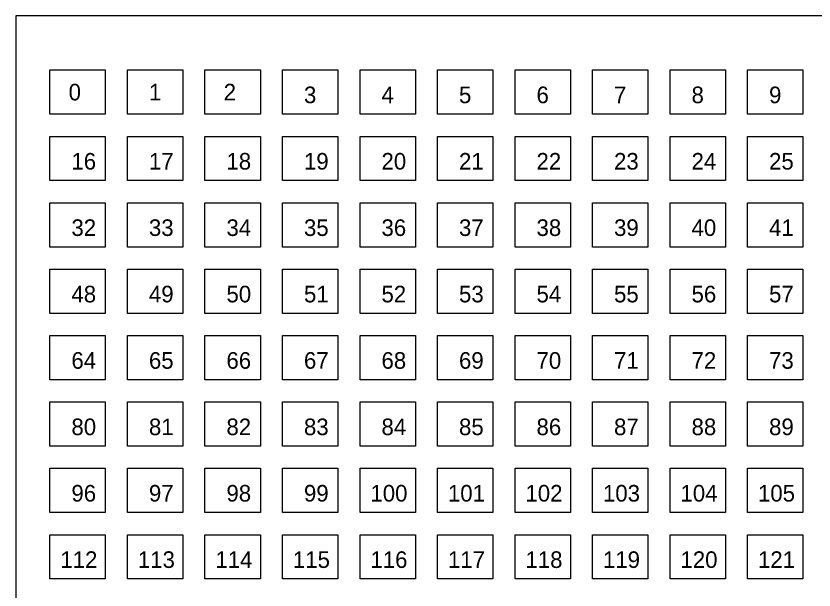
# Model space of a CAD drawing. Extents: x 11193 to 12507, y 10092 to 10555.
# Drawn here: x 11927 to 12215.3, y 10335 to 10542.6 of the extents above; entities that cross this region are included whole.
import ezdxf

# ---------------------------------------------------------------- set-up
doc = ezdxf.new("R2010")
doc.units = 0
for name, color, linetype in [('Level 1', 7, 'Continuous'), ('Level 3', 7, 'Continuous'), ('Level 62', 7, 'Continuous'), ('Level 63', 7, 'Continuous')]:
    doc.layers.add(name, color=color, linetype=linetype)

msp = doc.modelspace()

# ---------------------------------------------------------------- linework, layer by layer
at = {"layer": 'Level 1'}
msp.add_lwpolyline([(11939.26, 10459.04), (11939.26, 10475.04), (11959.26, 10475.04), (11959.26, 10459.04)], close=True, dxfattribs=at)
msp.add_lwpolyline([(11939.26, 10459.04), (11939.26, 10475.04), (11959.26, 10475.04), (11959.26, 10459.04)], close=True, dxfattribs=at)
at = {"layer": 'Level 3'}
msp.add_lwpolyline([(11926.98, 10137.56), (12506.98, 10137.56), (12506.98, 10542.56), (11926.98, 10542.56), (11926.98, 10137.56)], dxfattribs=at)
for points in [[(11939.26, 10507.04), (11939.26, 10523.04), (11959.26, 10523.04), (11959.26, 10507.04)], [(11967.26, 10507.04), (11967.26, 10523.04), (11987.26, 10523.04), (11987.26, 10507.04)], [(11995.26, 10507.04), (11995.26, 10523.04), (12015.26, 10523.04), (12015.26, 10507.04)], [(12023.26, 10507.04), (12023.26, 10523.04), (12043.26, 10523.04), (12043.26, 10507.04)], [(12051.26, 10507.04), (12051.26, 10523.04), (12071.26, 10523.04), (12071.26, 10507.04)], [(12079.26, 10507.04), (12079.26, 10523.04), (12099.26, 10523.04), (12099.26, 10507.04)], [(12107.26, 10507.04), (12107.26, 10523.04), (12127.26, 10523.04), (12127.26, 10507.04)], [(12135.26, 10507.04), (12135.26, 10523.04), (12155.26, 10523.04), (12155.26, 10507.04)], [(12163.26, 10507.04), (12163.26, 10523.04), (12183.26, 10523.04), (12183.26, 10507.04)], [(12191.26, 10507.04), (12191.26, 10523.04), (12211.26, 10523.04), (12211.26, 10507.04)], [(11939.26, 10483.04), (11939.26, 10499.04), (11959.26, 10499.04), (11959.26, 10483.04)], [(11967.26, 10483.04), (11967.26, 10499.04), (11987.26, 10499.04), (11987.26, 10483.04)], [(11995.26, 10483.04), (11995.26, 10499.04), (12015.26, 10499.04), (12015.26, 10483.04)], [(12023.26, 10483.04), (12023.26, 10499.04), (12043.26, 10499.04), (12043.26, 10483.04)], [(12051.26, 10483.04), (12051.26, 10499.04), (12071.26, 10499.04), (12071.26, 10483.04)], [(12079.26, 10483.04), (12079.26, 10499.04), (12099.26, 10499.04), (12099.26, 10483.04)], [(12107.26, 10483.04), (12107.26, 10499.04), (12127.26, 10499.04), (12127.26, 10483.04)], [(12135.26, 10483.04), (12135.26, 10499.04), (12155.26, 10499.04), (12155.26, 10483.04)], [(12163.26, 10483.04), (12163.26, 10499.04), (12183.26, 10499.04), (12183.26, 10483.04)], [(12191.26, 10483.04), (12191.26, 10499.04), (12211.26, 10499.04), (12211.26, 10483.04)], [(11967.26, 10459.04), (11967.26, 10475.04), (11987.26, 10475.04), (11987.26, 10459.04)], [(11995.26, 10459.04), (11995.26, 10475.04), (12015.26, 10475.04), (12015.26, 10459.04)], [(12023.26, 10459.04), (12023.26, 10475.04), (12043.26, 10475.04), (12043.26, 10459.04)], [(12051.26, 10459.04), (12051.26, 10475.04), (12071.26, 10475.04), (12071.26, 10459.04)], [(12079.26, 10459.04), (12079.26, 10475.04), (12099.26, 10475.04), (12099.26, 10459.04)], [(12107.26, 10459.04), (12107.26, 10475.04), (12127.26, 10475.04), (12127.26, 10459.04)], [(12135.26, 10459.04), (12135.26, 10475.04), (12155.26, 10475.04), (12155.26, 10459.04)], [(12163.26, 10459.04), (12163.26, 10475.04), (12183.26, 10475.04), (12183.26, 10459.04)], [(12191.26, 10459.04), (12191.26, 10475.04), (12211.26, 10475.04), (12211.26, 10459.04)], [(11939.26, 10435.04), (11939.26, 10451.04), (11959.26, 10451.04), (11959.26, 10435.04)], [(11967.26, 10435.04), (11967.26, 10451.04), (11987.26, 10451.04), (11987.26, 10435.04)], [(11995.26, 10435.04), (11995.26, 10451.04), (12015.26, 10451.04), (12015.26, 10435.04)], [(12023.26, 10435.04), (12023.26, 10451.04), (12043.26, 10451.04), (12043.26, 10435.04)], [(12051.26, 10435.04), (12051.26, 10451.04), (12071.26, 10451.04), (12071.26, 10435.04)], [(12079.26, 10435.04), (12079.26, 10451.04), (12099.26, 10451.04), (12099.26, 10435.04)], [(12107.26, 10435.04), (12107.26, 10451.04), (12127.26, 10451.04), (12127.26, 10435.04)], [(12135.26, 10435.04), (12135.26, 10451.04), (12155.26, 10451.04), (12155.26, 10435.04)], [(12163.26, 10435.04), (12163.26, 10451.04), (12183.26, 10451.04), (12183.26, 10435.04)], [(12191.26, 10435.04), (12191.26, 10451.04), (12211.26, 10451.04), (12211.26, 10435.04)], [(11939.26, 10411.04), (11939.26, 10427.04), (11959.26, 10427.04), (11959.26, 10411.04)], [(11967.26, 10411.04), (11967.26, 10427.04), (11987.26, 10427.04), (11987.26, 10411.04)], [(11995.26, 10411.04), (11995.26, 10427.04), (12015.26, 10427.04), (12015.26, 10411.04)], [(12023.26, 10411.04), (12023.26, 10427.04), (12043.26, 10427.04), (12043.26, 10411.04)], [(12051.26, 10411.04), (12051.26, 10427.04), (12071.26, 10427.04), (12071.26, 10411.04)], [(12079.26, 10411.04), (12079.26, 10427.04), (12099.26, 10427.04), (12099.26, 10411.04)], [(12107.26, 10411.04), (12107.26, 10427.04), (12127.26, 10427.04), (12127.26, 10411.04)], [(12135.26, 10411.04), (12135.26, 10427.04), (12155.26, 10427.04), (12155.26, 10411.04)], [(12163.26, 10411.04), (12163.26, 10427.04), (12183.26, 10427.04), (12183.26, 10411.04)], [(12191.26, 10411.04), (12191.26, 10427.04), (12211.26, 10427.04), (12211.26, 10411.04)], [(11939.26, 10387.04), (11939.26, 10403.04), (11959.26, 10403.04), (11959.26, 10387.04)], [(11967.26, 10387.04), (11967.26, 10403.04), (11987.26, 10403.04), (11987.26, 10387.04)], [(11995.26, 10387.04), (11995.26, 10403.04), (12015.26, 10403.04), (12015.26, 10387.04)], [(12023.26, 10387.04), (12023.26, 10403.04), (12043.26, 10403.04), (12043.26, 10387.04)], [(12051.26, 10387.04), (12051.26, 10403.04), (12071.26, 10403.04), (12071.26, 10387.04)], [(12079.26, 10387.04), (12079.26, 10403.04), (12099.26, 10403.04), (12099.26, 10387.04)], [(12107.26, 10387.04), (12107.26, 10403.04), (12127.26, 10403.04), (12127.26, 10387.04)], [(12135.26, 10387.04), (12135.26, 10403.04), (12155.26, 10403.04), (12155.26, 10387.04)], [(12163.26, 10387.04), (12163.26, 10403.04), (12183.26, 10403.04), (12183.26, 10387.04)], [(12191.26, 10387.04), (12191.26, 10403.04), (12211.26, 10403.04), (12211.26, 10387.04)], [(11939.26, 10363.04), (11939.26, 10379.04), (11959.26, 10379.04), (11959.26, 10363.04)], [(11967.26, 10363.04), (11967.26, 10379.04), (11987.26, 10379.04), (11987.26, 10363.04)], [(11995.26, 10363.04), (11995.26, 10379.04), (12015.26, 10379.04), (12015.26, 10363.04)], [(12023.26, 10363.04), (12023.26, 10379.04), (12043.26, 10379.04), (12043.26, 10363.04)], [(12051.26, 10363.04), (12051.26, 10379.04), (12071.26, 10379.04), (12071.26, 10363.04)], [(12079.26, 10363.04), (12079.26, 10379.04), (12099.26, 10379.04), (12099.26, 10363.04)], [(12107.26, 10363.04), (12107.26, 10379.04), (12127.26, 10379.04), (12127.26, 10363.04)], [(12135.26, 10363.04), (12135.26, 10379.04), (12155.26, 10379.04), (12155.26, 10363.04)], [(12163.26, 10363.04), (12163.26, 10379.04), (12183.26, 10379.04), (12183.26, 10363.04)], [(12191.26, 10363.04), (12191.26, 10379.04), (12211.26, 10379.04), (12211.26, 10363.04)], [(11939.26, 10339.04), (11939.26, 10355.04), (11959.26, 10355.04), (11959.26, 10339.04)], [(11967.26, 10339.04), (11967.26, 10355.04), (11987.26, 10355.04), (11987.26, 10339.04)], [(11995.26, 10339.04), (11995.26, 10355.04), (12015.26, 10355.04), (12015.26, 10339.04)], [(12023.26, 10339.04), (12023.26, 10355.04), (12043.26, 10355.04), (12043.26, 10339.04)], [(12051.26, 10339.04), (12051.26, 10355.04), (12071.26, 10355.04), (12071.26, 10339.04)], [(12079.26, 10339.04), (12079.26, 10355.04), (12099.26, 10355.04), (12099.26, 10339.04)], [(12107.26, 10339.04), (12107.26, 10355.04), (12127.26, 10355.04), (12127.26, 10339.04)], [(12135.26, 10339.04), (12135.26, 10355.04), (12155.26, 10355.04), (12155.26, 10339.04)], [(12163.26, 10339.04), (12163.26, 10355.04), (12183.26, 10355.04), (12183.26, 10339.04)], [(12191.26, 10339.04), (12191.26, 10355.04), (12211.26, 10355.04), (12211.26, 10339.04)]]:
    msp.add_lwpolyline(points, close=True, dxfattribs=at)
at = {"layer": 'Level 63'}
for points in [[(11939.26, 10507.04), (11939.26, 10523.04), (11959.26, 10523.04), (11959.26, 10507.04)], [(11967.26, 10507.04), (11967.26, 10523.04), (11987.26, 10523.04), (11987.26, 10507.04)], [(11995.26, 10507.04), (11995.26, 10523.04), (12015.26, 10523.04), (12015.26, 10507.04)], [(12023.26, 10507.04), (12023.26, 10523.04), (12043.26, 10523.04), (12043.26, 10507.04)], [(12051.26, 10507.04), (12051.26, 10523.04), (12071.26, 10523.04), (12071.26, 10507.04)], [(12079.26, 10507.04), (12079.26, 10523.04), (12099.26, 10523.04), (12099.26, 10507.04)], [(12107.26, 10507.04), (12107.26, 10523.04), (12127.26, 10523.04), (12127.26, 10507.04)], [(12135.26, 10507.04), (12135.26, 10523.04), (12155.26, 10523.04), (12155.26, 10507.04)], [(12163.26, 10507.04), (12163.26, 10523.04), (12183.26, 10523.04), (12183.26, 10507.04)], [(12191.26, 10507.04), (12191.26, 10523.04), (12211.26, 10523.04), (12211.26, 10507.04)], [(11939.26, 10483.04), (11939.26, 10499.04), (11959.26, 10499.04), (11959.26, 10483.04)], [(11967.26, 10483.04), (11967.26, 10499.04), (11987.26, 10499.04), (11987.26, 10483.04)], [(11995.26, 10483.04), (11995.26, 10499.04), (12015.26, 10499.04), (12015.26, 10483.04)], [(12023.26, 10483.04), (12023.26, 10499.04), (12043.26, 10499.04), (12043.26, 10483.04)], [(12051.26, 10483.04), (12051.26, 10499.04), (12071.26, 10499.04), (12071.26, 10483.04)], [(12079.26, 10483.04), (12079.26, 10499.04), (12099.26, 10499.04), (12099.26, 10483.04)], [(12107.26, 10483.04), (12107.26, 10499.04), (12127.26, 10499.04), (12127.26, 10483.04)], [(12135.26, 10483.04), (12135.26, 10499.04), (12155.26, 10499.04), (12155.26, 10483.04)], [(12163.26, 10483.04), (12163.26, 10499.04), (12183.26, 10499.04), (12183.26, 10483.04)], [(12191.26, 10483.04), (12191.26, 10499.04), (12211.26, 10499.04), (12211.26, 10483.04)], [(11939.26, 10459.04), (11939.26, 10475.04), (11959.26, 10475.04), (11959.26, 10459.04)], [(11967.26, 10459.04), (11967.26, 10475.04), (11987.26, 10475.04), (11987.26, 10459.04)], [(11995.26, 10459.04), (11995.26, 10475.04), (12015.26, 10475.04), (12015.26, 10459.04)], [(12023.26, 10459.04), (12023.26, 10475.04), (12043.26, 10475.04), (12043.26, 10459.04)], [(12051.26, 10459.04), (12051.26, 10475.04), (12071.26, 10475.04), (12071.26, 10459.04)], [(12079.26, 10459.04), (12079.26, 10475.04), (12099.26, 10475.04), (12099.26, 10459.04)], [(12107.26, 10459.04), (12107.26, 10475.04), (12127.26, 10475.04), (12127.26, 10459.04)], [(12135.26, 10459.04), (12135.26, 10475.04), (12155.26, 10475.04), (12155.26, 10459.04)], [(12163.26, 10459.04), (12163.26, 10475.04), (12183.26, 10475.04), (12183.26, 10459.04)], [(12191.26, 10459.04), (12191.26, 10475.04), (12211.26, 10475.04), (12211.26, 10459.04)], [(11939.26, 10435.04), (11939.26, 10451.04), (11959.26, 10451.04), (11959.26, 10435.04)], [(11967.26, 10435.04), (11967.26, 10451.04), (11987.26, 10451.04), (11987.26, 10435.04)], [(11995.26, 10435.04), (11995.26, 10451.04), (12015.26, 10451.04), (12015.26, 10435.04)], [(12023.26, 10435.04), (12023.26, 10451.04), (12043.26, 10451.04), (12043.26, 10435.04)], [(12051.26, 10435.04), (12051.26, 10451.04), (12071.26, 10451.04), (12071.26, 10435.04)], [(12079.26, 10435.04), (12079.26, 10451.04), (12099.26, 10451.04), (12099.26, 10435.04)], [(12107.26, 10435.04), (12107.26, 10451.04), (12127.26, 10451.04), (12127.26, 10435.04)], [(12135.26, 10435.04), (12135.26, 10451.04), (12155.26, 10451.04), (12155.26, 10435.04)], [(12163.26, 10435.04), (12163.26, 10451.04), (12183.26, 10451.04), (12183.26, 10435.04)], [(12191.26, 10435.04), (12191.26, 10451.04), (12211.26, 10451.04), (12211.26, 10435.04)], [(11939.26, 10411.04), (11939.26, 10427.04), (11959.26, 10427.04), (11959.26, 10411.04)], [(11967.26, 10411.04), (11967.26, 10427.04), (11987.26, 10427.04), (11987.26, 10411.04)], [(11995.26, 10411.04), (11995.26, 10427.04), (12015.26, 10427.04), (12015.26, 10411.04)], [(12023.26, 10411.04), (12023.26, 10427.04), (12043.26, 10427.04), (12043.26, 10411.04)], [(12051.26, 10411.04), (12051.26, 10427.04), (12071.26, 10427.04), (12071.26, 10411.04)], [(12079.26, 10411.04), (12079.26, 10427.04), (12099.26, 10427.04), (12099.26, 10411.04)], [(12107.26, 10411.04), (12107.26, 10427.04), (12127.26, 10427.04), (12127.26, 10411.04)], [(12135.26, 10411.04), (12135.26, 10427.04), (12155.26, 10427.04), (12155.26, 10411.04)], [(12163.26, 10411.04), (12163.26, 10427.04), (12183.26, 10427.04), (12183.26, 10411.04)], [(12191.26, 10411.04), (12191.26, 10427.04), (12211.26, 10427.04), (12211.26, 10411.04)], [(11939.26, 10387.04), (11939.26, 10403.04), (11959.26, 10403.04), (11959.26, 10387.04)], [(11967.26, 10387.04), (11967.26, 10403.04), (11987.26, 10403.04), (11987.26, 10387.04)], [(11995.26, 10387.04), (11995.26, 10403.04), (12015.26, 10403.04), (12015.26, 10387.04)], [(12023.26, 10387.04), (12023.26, 10403.04), (12043.26, 10403.04), (12043.26, 10387.04)], [(12051.26, 10387.04), (12051.26, 10403.04), (12071.26, 10403.04), (12071.26, 10387.04)], [(12079.26, 10387.04), (12079.26, 10403.04), (12099.26, 10403.04), (12099.26, 10387.04)], [(12107.26, 10387.04), (12107.26, 10403.04), (12127.26, 10403.04), (12127.26, 10387.04)], [(12135.26, 10387.04), (12135.26, 10403.04), (12155.26, 10403.04), (12155.26, 10387.04)], [(12163.26, 10387.04), (12163.26, 10403.04), (12183.26, 10403.04), (12183.26, 10387.04)], [(12191.26, 10387.04), (12191.26, 10403.04), (12211.26, 10403.04), (12211.26, 10387.04)], [(11939.26, 10363.04), (11939.26, 10379.04), (11959.26, 10379.04), (11959.26, 10363.04)], [(11967.26, 10363.04), (11967.26, 10379.04), (11987.26, 10379.04), (11987.26, 10363.04)], [(11995.26, 10363.04), (11995.26, 10379.04), (12015.26, 10379.04), (12015.26, 10363.04)], [(12023.26, 10363.04), (12023.26, 10379.04), (12043.26, 10379.04), (12043.26, 10363.04)], [(12051.26, 10363.04), (12051.26, 10379.04), (12071.26, 10379.04), (12071.26, 10363.04)], [(12079.26, 10363.04), (12079.26, 10379.04), (12099.26, 10379.04), (12099.26, 10363.04)], [(12107.26, 10363.04), (12107.26, 10379.04), (12127.26, 10379.04), (12127.26, 10363.04)], [(12135.26, 10363.04), (12135.26, 10379.04), (12155.26, 10379.04), (12155.26, 10363.04)], [(12163.26, 10363.04), (12163.26, 10379.04), (12183.26, 10379.04), (12183.26, 10363.04)], [(12191.26, 10363.04), (12191.26, 10379.04), (12211.26, 10379.04), (12211.26, 10363.04)], [(11939.26, 10339.04), (11939.26, 10355.04), (11959.26, 10355.04), (11959.26, 10339.04)], [(11967.26, 10339.04), (11967.26, 10355.04), (11987.26, 10355.04), (11987.26, 10339.04)], [(11995.26, 10339.04), (11995.26, 10355.04), (12015.26, 10355.04), (12015.26, 10339.04)], [(12023.26, 10339.04), (12023.26, 10355.04), (12043.26, 10355.04), (12043.26, 10339.04)], [(12051.26, 10339.04), (12051.26, 10355.04), (12071.26, 10355.04), (12071.26, 10339.04)], [(12079.26, 10339.04), (12079.26, 10355.04), (12099.26, 10355.04), (12099.26, 10339.04)], [(12107.26, 10339.04), (12107.26, 10355.04), (12127.26, 10355.04), (12127.26, 10339.04)], [(12135.26, 10339.04), (12135.26, 10355.04), (12155.26, 10355.04), (12155.26, 10339.04)], [(12163.26, 10339.04), (12163.26, 10355.04), (12183.26, 10355.04), (12183.26, 10339.04)], [(12191.26, 10339.04), (12191.26, 10355.04), (12211.26, 10355.04), (12211.26, 10339.04)]]:
    msp.add_lwpolyline(points, close=True, dxfattribs=at)

# ---------------------------------------------------------------- texts
at = {"layer": 'Level 62'}
for s, p in [('0', (11946.01, 10512.03)), ('1', (11975.01, 10512.03)), ('2', (12002.01, 10512.03)), ('3', (12031.01, 10511.03)), ('4', (12059.01, 10511.03)), ('5', (12087.01, 10511.03)), ('6', (12115.01, 10511.03)), ('7', (12143.01, 10511.03)), ('8', (12171.01, 10511.03)), ('9', (12199.01, 10511.03)), ('16', (11947.01, 10487.03)), ('17', (11975.01, 10487.03)), ('18', (12003.01, 10487.03)), ('19', (12031.01, 10487.03)), ('20', (12059.01, 10487.03)), ('21', (12087.01, 10487.03)), ('22', (12115.01, 10487.03)), ('23', (12143.01, 10487.03)), ('24', (12171.01, 10487.03)), ('25', (12199.01, 10487.03)), ('32', (11947.01, 10463.03)), ('33', (11975.01, 10463.03)), ('34', (12003.01, 10463.03)), ('35', (12031.01, 10463.03)), ('36', (12059.01, 10463.03)), ('37', (12087.01, 10463.03)), ('38', (12115.01, 10463.03)), ('39', (12143.01, 10463.03)), ('40', (12171.01, 10463.03)), ('41', (12199.01, 10463.03)), ('48', (11947.01, 10439.03)), ('49', (11975.01, 10439.03)), ('50', (12003.01, 10439.03)), ('51', (12031.01, 10439.03)), ('52', (12059.01, 10439.03)), ('53', (12087.01, 10439.03)), ('54', (12115.01, 10439.03)), ('55', (12143.01, 10439.03)), ('56', (12171.01, 10439.03)), ('57', (12199.01, 10439.03)), ('64', (11947.01, 10415.03)), ('65', (11975.01, 10415.03)), ('66', (12003.01, 10415.03)), ('67', (12031.01, 10415.03)), ('68', (12059.01, 10415.03)), ('69', (12087.01, 10415.03)), ('70', (12115.01, 10415.03)), ('71', (12143.01, 10415.03)), ('72', (12171.01, 10415.03)), ('73', (12199.01, 10415.03)), ('80', (11947.01, 10391.03)), ('81', (11975.01, 10391.03)), ('82', (12003.01, 10391.03)), ('83', (12031.01, 10391.03)), ('84', (12059.01, 10391.03)), ('85', (12087.01, 10391.03)), ('86', (12115.01, 10391.03)), ('87', (12143.01, 10391.03)), ('88', (12171.01, 10391.03)), ('89', (12199.01, 10391.03)), ('96', (11947.01, 10367.03)), ('97', (11975.01, 10367.03)), ('98', (12003.01, 10367.03)), ('99', (12031.01, 10367.03)), ('100', (12055.01, 10367.03)), ('101', (12083.01, 10367.03)), ('102', (12111.01, 10367.03)), ('103', (12139.01, 10367.03)), ('104', (12167.01, 10367.03)), ('105', (12195.01, 10367.03)), ('112', (11943.01, 10343.03)), ('113', (11971.01, 10343.03)), ('114', (11999.01, 10343.03)), ('115', (12027.01, 10343.03)), ('116', (12055.01, 10343.03)), ('117', (12083.01, 10343.03)), ('118', (12111.01, 10343.03)), ('119', (12139.01, 10343.03)), ('120', (12167.01, 10343.03)), ('121', (12195.01, 10343.03))]:
    msp.add_text(s, height=6, dxfattribs=at).set_placement(p)

doc.saveas('drawing.dxf')
